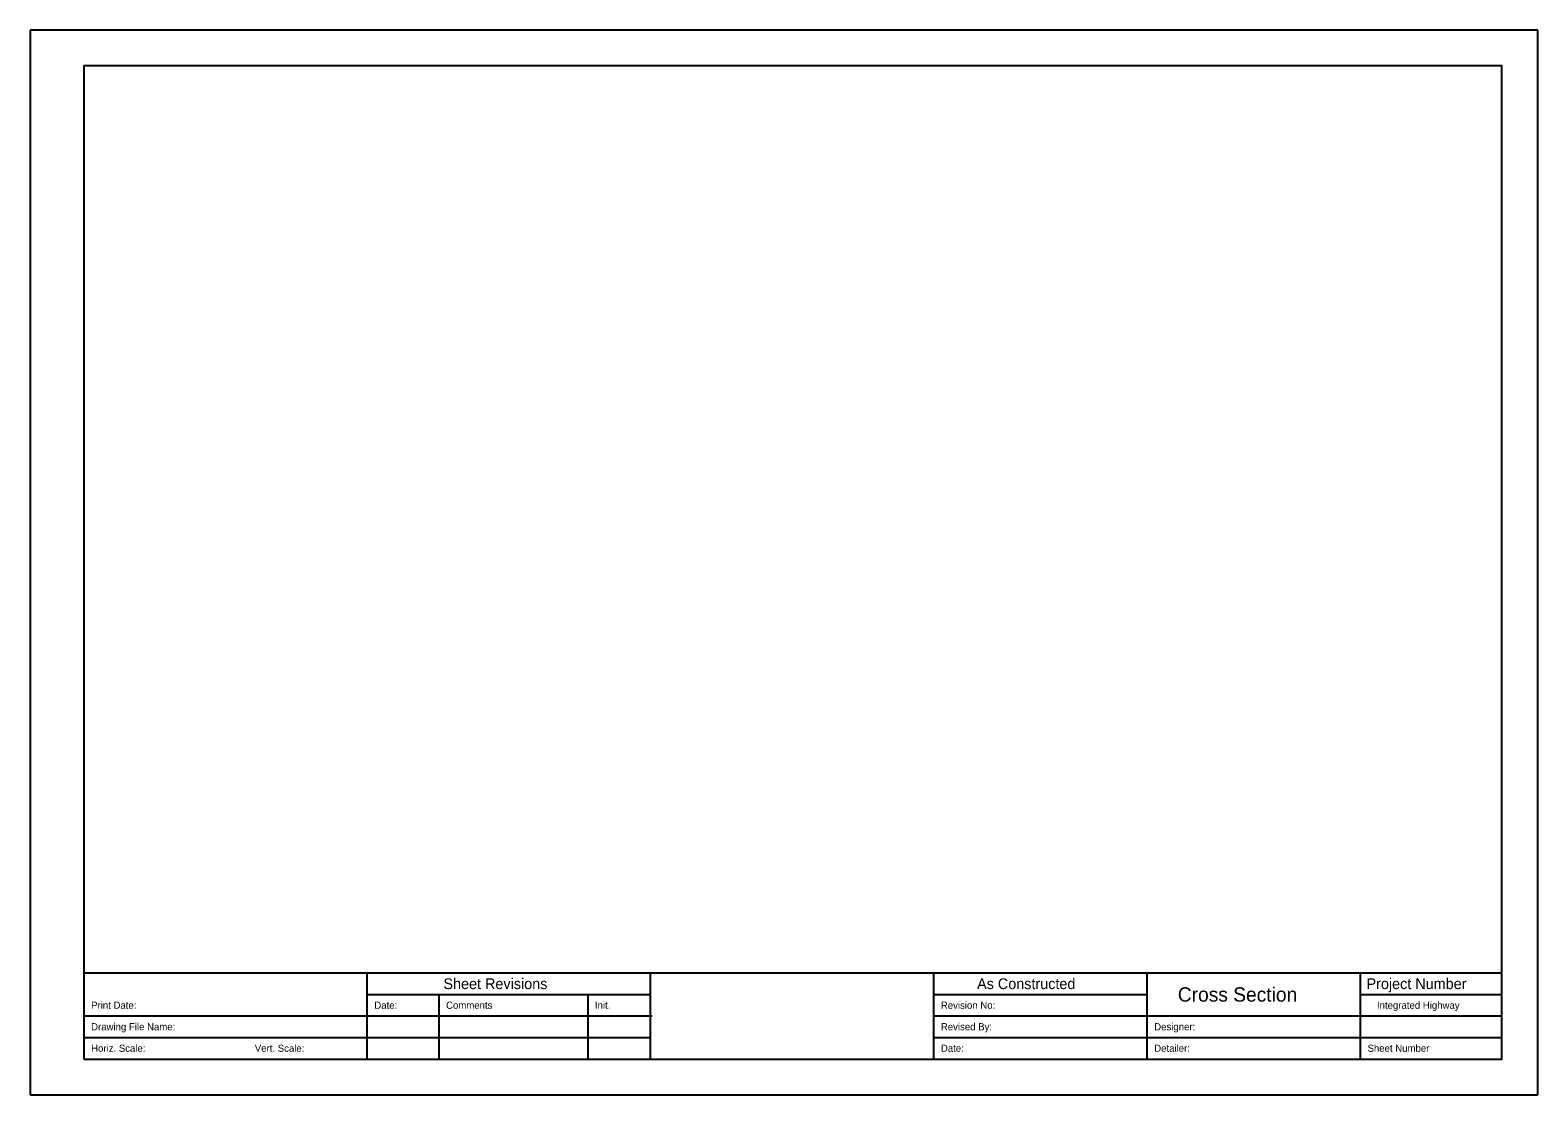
# Model space of a CAD drawing. Extents: x 0 to 0.841, y 0 to 0.594.
import ezdxf

# ---------------------------------------------------------------- set-up
doc = ezdxf.new("R2010")
doc.units = 0
doc.layers.add('Draft_Sheet', color=7, linetype='Continuous')

msp = doc.modelspace()

# ---------------------------------------------------------------- linework, layer by layer
at = {"layer": 'Draft_Sheet'}
for p, q in [((0.841, 0.594), (0, 0.594)), ((0, 0.594), (0, 0)), ((0.841, 0), (0.841, 0.594)), ((0.03, 0.068), (0.821, 0.068)), ((0.188, 0.02), (0.188, 0.068)), ((0.346, 0.02), (0.346, 0.068)), ((0.504, 0.02), (0.504, 0.068)), ((0.623, 0.02), (0.623, 0.068)), ((0.742, 0.02), (0.742, 0.068)), ((0.188, 0.056), (0.346, 0.056)), ((0.228, 0.056), (0.228, 0.02)), ((0.311, 0.056), (0.311, 0.02)), ((0.504, 0.056), (0.623, 0.056)), ((0.742, 0.056), (0.821, 0.056)), ((0.03, 0.044), (0.347, 0.044)), ((0.504, 0.044), (0.821, 0.044)), ((0.03, 0.032), (0.346, 0.032)), ((0.504, 0.032), (0.821, 0.032)), ((0, 0), (0.841, 0))]:
    msp.add_line(p, q, dxfattribs=at)
msp.add_lwpolyline([(0.03, 0.02), (0.821, 0.02), (0.821, 0.574), (0.03, 0.574)], close=True, dxfattribs=at)

# ---------------------------------------------------------------- texts
for s, height, p in [('Sheet Revisions', 0.006, (0.23054, 0.059)), ('As Constructed', 0.006, (0.5282, 0.059)), ('Cross Section', 0.008, (0.64018, 0.052)), ('Project Number', 0.006, (0.74544, 0.059)), ('Print Date:', 0.004, (0.034, 0.048)), ('Date:', 0.004, (0.192, 0.048)), ('Comments', 0.004, (0.232, 0.048)), ('Init.', 0.004, (0.315, 0.048)), ('Revision No:', 0.004, (0.508, 0.048)), ('Integrated Highway', 0.004, (0.75126, 0.048)), ('Drawing File Name:', 0.004, (0.034, 0.036)), ('Revised By:', 0.004, (0.508, 0.036)), ('Designer:', 0.004, (0.627, 0.036)), ('Horiz. Scale:', 0.004, (0.034, 0.024)), ('Vert. Scale:', 0.004, (0.12532, 0.024)), ('Date:', 0.004, (0.508, 0.024)), ('Detailer:', 0.004, (0.627, 0.024)), ('Sheet Number', 0.004, (0.746, 0.024))]:
    msp.add_text(s, height=height, dxfattribs=at).set_placement(p)

doc.saveas('drawing.dxf')
